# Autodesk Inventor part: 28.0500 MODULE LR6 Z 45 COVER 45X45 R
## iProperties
Created: 2007-06
Part Number: 28.0500 MODULE LR6 Z 45 COVER 45X45 R
Material: PVC-U
Document SubType Name: Modeling
Designer: Andy Moles
Density: 1.4 g/cm^3
Author: Andy Moles
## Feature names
1. Extrusion1
